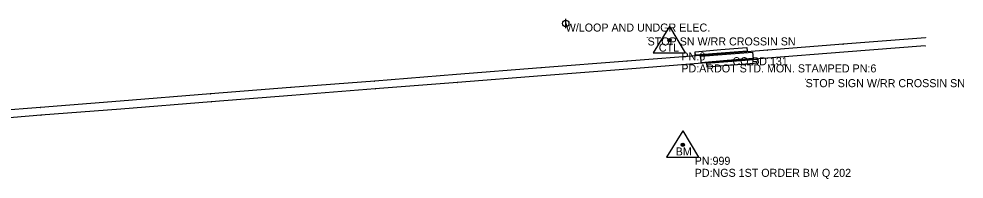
# Model space of a CAD drawing. Extents: x 878399 to 889864, y 1564003 to 1567413.
# Drawn here: x 885515 to 886105, y 1565495 to 1565595 of the extents above; entities that cross this region are included whole.
import ezdxf

# ---------------------------------------------------------------- set-up
doc = ezdxf.new("R2010")
doc.units = 0
for name, color, linetype in [('S_MSC_PT_SYM', 7, 'Continuous'), ('S_PRIMARY_CTL', 7, 'Continuous'), ('S_PRIMARY_CTL_ANNOT', 7, 'Continuous'), ('S_RAILROAD', 7, 'Continuous'), ('S_SURVEY_TEXT_ANNOT', 7, 'Continuous'), ('S_UTILITY_POLE', 7, 'Continuous'), ('S_UTILITY_POLE_ANNOT', 7, 'Continuous')]:
    doc.layers.add(name, color=color, linetype=linetype)

msp = doc.modelspace()

# ---------------------------------------------------------------- linework, layer by layer
at = {"layer": 'S_MSC_PT_SYM'}
for points in [[(885907.33, 1565583.67), (885907.33, 1565583.72), (885907.33, 1565583.67), (885907.28, 1565583.67), (885907.33, 1565583.67), (885907.33, 1565583.62), (885907.33, 1565583.67), (885907.38, 1565583.67)], [(886080.97, 1565583.46), (886080.97, 1565583.51), (886080.97, 1565583.46), (886080.92, 1565583.46), (886080.97, 1565583.46), (886080.97, 1565583.41), (886080.97, 1565583.46), (886081.02, 1565583.46)], [(886029.46, 1565579.39), (886029.46, 1565579.44), (886029.46, 1565579.39), (886029.41, 1565579.39), (886029.46, 1565579.39), (886029.46, 1565579.34), (886029.46, 1565579.39), (886029.51, 1565579.39)], [(886080.84, 1565578.47), (886080.84, 1565578.52), (886080.84, 1565578.47), (886080.79, 1565578.47), (886080.84, 1565578.47), (886080.84, 1565578.42), (886080.84, 1565578.47), (886080.89, 1565578.47)], [(885943.15, 1565572.71), (885943.15, 1565572.76), (885943.15, 1565572.71), (885943.1, 1565572.71), (885943.15, 1565572.71), (885943.15, 1565572.66), (885943.15, 1565572.71), (885943.2, 1565572.71)], [(885960.38, 1565571.33), (885960.38, 1565571.38), (885960.38, 1565571.33), (885960.33, 1565571.33), (885960.38, 1565571.33), (885960.38, 1565571.28), (885960.38, 1565571.33), (885960.43, 1565571.33)], [(885982.34, 1565570.76), (885982.34, 1565570.81), (885982.34, 1565570.76), (885982.29, 1565570.76), (885982.34, 1565570.76), (885982.34, 1565570.71), (885982.34, 1565570.76), (885982.39, 1565570.76)], [(885982.39, 1565575.78), (885982.39, 1565575.83), (885982.39, 1565575.78), (885982.34, 1565575.78), (885982.39, 1565575.78), (885982.39, 1565575.73), (885982.39, 1565575.78), (885982.44, 1565575.78)], [(886029.9, 1565574.49), (886029.9, 1565574.54), (886029.9, 1565574.49), (886029.85, 1565574.49), (886029.9, 1565574.49), (886029.9, 1565574.44), (886029.9, 1565574.49), (886029.95, 1565574.49)], [(885894.52, 1565568.86), (885894.52, 1565568.91), (885894.52, 1565568.86), (885894.47, 1565568.86), (885894.52, 1565568.86), (885894.52, 1565568.81), (885894.52, 1565568.86), (885894.57, 1565568.86)], [(885944.07, 1565567.81), (885944.07, 1565567.86), (885944.07, 1565567.81), (885944.02, 1565567.81), (885944.07, 1565567.81), (885944.07, 1565567.76), (885944.07, 1565567.81), (885944.12, 1565567.81)], [(885787.97, 1565560.53), (885787.97, 1565560.58), (885787.97, 1565560.53), (885787.92, 1565560.53), (885787.97, 1565560.53), (885787.97, 1565560.48), (885787.97, 1565560.53), (885788.02, 1565560.53)], [(885840.62, 1565564.65), (885840.62, 1565564.7), (885840.62, 1565564.65), (885840.57, 1565564.65), (885840.62, 1565564.65), (885840.62, 1565564.6), (885840.62, 1565564.65), (885840.67, 1565564.65)], [(885841.29, 1565559.7), (885841.29, 1565559.75), (885841.29, 1565559.7), (885841.24, 1565559.7), (885841.29, 1565559.7), (885841.29, 1565559.65), (885841.29, 1565559.7), (885841.34, 1565559.7)], [(885894.96, 1565563.95), (885894.96, 1565564), (885894.96, 1565563.95), (885894.91, 1565563.95), (885894.96, 1565563.95), (885894.96, 1565563.9), (885894.96, 1565563.95), (885895.01, 1565563.95)], [(885736.83, 1565556.51), (885736.83, 1565556.56), (885736.83, 1565556.51), (885736.78, 1565556.51), (885736.83, 1565556.51), (885736.83, 1565556.46), (885736.83, 1565556.51), (885736.88, 1565556.51)], [(885788.48, 1565555.58), (885788.48, 1565555.63), (885788.48, 1565555.58), (885788.43, 1565555.58), (885788.48, 1565555.58), (885788.48, 1565555.53), (885788.48, 1565555.58), (885788.53, 1565555.58)], [(886006.08, 1565557.67), (886006.08, 1565557.72), (886006.08, 1565557.67), (886006.03, 1565557.67), (886006.08, 1565557.67), (886006.08, 1565557.62), (886006.08, 1565557.67), (886006.13, 1565557.67)], [(885634.17, 1565548.45), (885634.17, 1565548.5), (885634.17, 1565548.45), (885634.12, 1565548.45), (885634.17, 1565548.45), (885634.17, 1565548.4), (885634.17, 1565548.45), (885634.22, 1565548.45)], [(885684.23, 1565552.37), (885684.23, 1565552.42), (885684.23, 1565552.37), (885684.18, 1565552.37), (885684.23, 1565552.37), (885684.23, 1565552.32), (885684.23, 1565552.37), (885684.28, 1565552.37)], [(885685.02, 1565547.46), (885685.02, 1565547.51), (885685.02, 1565547.46), (885684.97, 1565547.46), (885685.02, 1565547.46), (885685.02, 1565547.41), (885685.02, 1565547.46), (885685.07, 1565547.46)], [(885737.19, 1565551.59), (885737.19, 1565551.64), (885737.19, 1565551.59), (885737.14, 1565551.59), (885737.19, 1565551.59), (885737.19, 1565551.54), (885737.19, 1565551.59), (885737.24, 1565551.59)], [(885577.79, 1565544), (885577.79, 1565544.05), (885577.79, 1565544), (885577.74, 1565544), (885577.79, 1565544), (885577.79, 1565543.95), (885577.79, 1565544), (885577.84, 1565544)], [(885634.71, 1565543.52), (885634.71, 1565543.57), (885634.71, 1565543.52), (885634.66, 1565543.52), (885634.71, 1565543.52), (885634.71, 1565543.47), (885634.71, 1565543.52), (885634.76, 1565543.52)], [(885527.93, 1565540.08), (885527.93, 1565540.13), (885527.93, 1565540.08), (885527.88, 1565540.08), (885527.93, 1565540.08), (885527.93, 1565540.03), (885527.93, 1565540.08), (885527.98, 1565540.08)], [(885578.21, 1565539.07), (885578.21, 1565539.12), (885578.21, 1565539.07), (885578.16, 1565539.07), (885578.21, 1565539.07), (885578.21, 1565539.02), (885578.21, 1565539.07), (885578.26, 1565539.07)], [(885528.29, 1565535.15), (885528.29, 1565535.2), (885528.29, 1565535.15), (885528.24, 1565535.15), (885528.29, 1565535.15), (885528.29, 1565535.1), (885528.29, 1565535.15), (885528.34, 1565535.15)]]:
    msp.add_lwpolyline(points, dxfattribs=at)
at = {"layer": 'S_PRIMARY_CTL'}
for p, q in [((885920.94, 1565590.56), (885910.91, 1565574.05)), ((885920.94, 1565590.56), (885930.77, 1565574.05)), ((885910.91, 1565574.05), (885930.77, 1565574.05)), ((885929.26, 1565525.52), (885919.23, 1565509.01)), ((885929.26, 1565525.52), (885939.08, 1565509.01)), ((885919.23, 1565509.01), (885939.08, 1565509.01))]:
    msp.add_line(p, q, dxfattribs=at)
for centre, radius in [((885920.94, 1565581.86), 1.04), ((885920.94, 1565581.86), 0.609), ((885920.94, 1565581.86), 0.344), ((885929.26, 1565516.82), 1.04), ((885929.26, 1565516.82), 0.609), ((885929.26, 1565516.82), 0.344)]:
    msp.add_circle(centre, radius, dxfattribs=at)
at = {"layer": 'S_RAILROAD'}
for p, q in [((886080.97, 1565583.46), (886029.46, 1565579.39)), ((886029.46, 1565579.39), (885982.39, 1565575.78)), ((886080.84, 1565578.47), (886029.9, 1565574.49)), ((885943.15, 1565572.71), (885894.52, 1565568.86)), ((885982.39, 1565575.78), (885943.15, 1565572.71)), ((885982.34, 1565570.76), (885944.07, 1565567.81)), ((886029.9, 1565574.49), (885982.34, 1565570.76)), ((885894.52, 1565568.86), (885840.62, 1565564.65)), ((885944.07, 1565567.81), (885894.96, 1565563.95)), ((885787.97, 1565560.53), (885736.83, 1565556.51)), ((885840.62, 1565564.65), (885787.97, 1565560.53)), ((885841.29, 1565559.7), (885788.48, 1565555.58)), ((885894.96, 1565563.95), (885841.29, 1565559.7)), ((885736.83, 1565556.51), (885684.23, 1565552.37)), ((885788.48, 1565555.58), (885737.19, 1565551.59)), ((885634.17, 1565548.45), (885577.79, 1565544)), ((885684.23, 1565552.37), (885634.17, 1565548.45)), ((885685.02, 1565547.46), (885634.71, 1565543.52)), ((885737.19, 1565551.59), (885685.02, 1565547.46)), ((885577.79, 1565544), (885527.93, 1565540.08)), ((885634.71, 1565543.52), (885578.21, 1565539.07)), ((885527.93, 1565540.08), (885477.1, 1565536.1)), ((885578.21, 1565539.07), (885528.29, 1565535.15)), ((885528.29, 1565535.15), (885477.65, 1565531.19))]:
    msp.add_line(p, q, dxfattribs=at)
for points in [[(885937.2, 1565572.59), (885937.01, 1565574.74), (885953.19, 1565576.05), (885969.37, 1565577.35), (885969.56, 1565575.16), (885953.38, 1565573.87)], [(885972.86, 1565574.58), (885973.2, 1565570.5), (885957.02, 1565569.22), (885940.83, 1565567.93), (885940.5, 1565572.06), (885956.68, 1565573.32)], [(885944.11, 1565567.42), (885944.28, 1565565.27), (885960.46, 1565566.54), (885976.64, 1565567.81), (885976.46, 1565569.93), (885960.28, 1565568.68)]]:
    msp.add_lwpolyline(points, close=True, dxfattribs=at)
at = {"layer": 'S_UTILITY_POLE'}
msp.add_line((885856.17, 1565589.37), (885856.17, 1565595.16), dxfattribs=at)
msp.add_circle((885856.17, 1565592.3), 2.05, dxfattribs=at)

# ---------------------------------------------------------------- texts
at = {"layer": 'S_PRIMARY_CTL'}
for s, p in [('CTL', (885914.36, 1565574.79)), ('BM', (885924.89, 1565510.12))]:
    msp.add_text(s, height=5, rotation=360, dxfattribs=at).set_placement(p)
at = {"layer": 'S_PRIMARY_CTL_ANNOT'}
for s, p in [('PN:6', (885928.44, 1565569.36)), ('PD:ARDOT STD. MON. STAMPED PN:6', (885928.44, 1565561.86)), ('PN:999', (885936.76, 1565504.32)), ('PD:NGS 1ST ORDER BM Q 202', (885936.76, 1565496.82))]:
    msp.add_text(s, height=5, dxfattribs=at).set_placement(p)
at = {"layer": 'S_SURVEY_TEXT_ANNOT'}
for s, p in [('STOP SN W/RR CROSSIN SN', (885907.33, 1565578.67)), ('CO RD 131', (885960.38, 1565566.33)), ('STOP SIGN W/RR CROSSIN SN', (886006.08, 1565552.67))]:
    msp.add_text(s, height=5, dxfattribs=at).set_placement(p)
at = {"layer": 'S_UTILITY_POLE_ANNOT'}
msp.add_text('W/LOOP AND UNDGR ELEC.', height=5, dxfattribs=at).set_placement((885856.17, 1565587.3))

doc.saveas('drawing.dxf')
